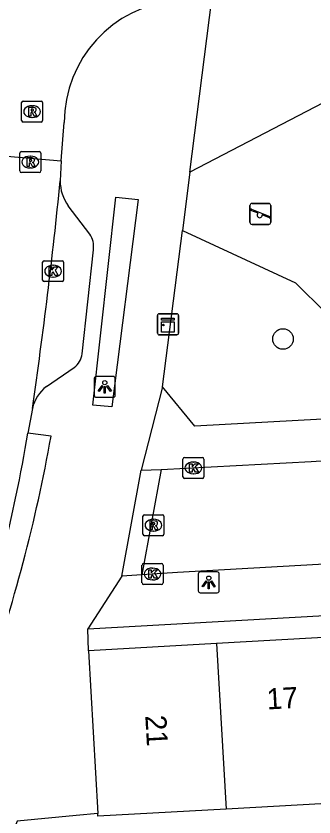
# Model space of a CAD drawing. Extents: x 163010 to 163853, y 382793 to 383982.
# Drawn here: x 163432.08 to 163446.26, y 383532.53 to 383570.74 of the extents above; entities that cross this region are included whole.
import ezdxf

# ---------------------------------------------------------------- set-up
doc = ezdxf.new("R2010")
doc.units = 0
for name, color, linetype in [('IMGEO_Boom', 7, 'Continuous'), ('IMGEO_Groenvoorziening', 7, 'Continuous'), ('IMGEO_Hek', 7, 'Continuous'), ('IMGEO_Kast', 7, 'Continuous'), ('IMGEO_Kolk', 7, 'Continuous'), ('IMGEO_Lichtpunt', 7, 'Continuous'), ('IMGEO_Pand', 7, 'Continuous'), ('IMGEO_Pand_nummerreeks', 7, 'Continuous'), ('IMGEO_Rijbaan_lokaal_gesloten', 7, 'Continuous'), ('IMGEO_Rijbaan_lokaal_open', 7, 'Continuous'), ('IMGEO_Rioolput', 7, 'Continuous'), ('IMGEO_Speelvoorziening', 7, 'Continuous'), ('IMGEO_Voetpad_open', 7, 'Continuous')]:
    doc.layers.add(name, color=color, linetype=linetype)

msp = doc.modelspace()

# ---------------------------------------------------------------- linework, layer by layer
at = {"layer": 'IMGEO_Boom'}
msp.add_circle((163444.789, 383555.331), 0.489, dxfattribs=at)
at = {"layer": 'IMGEO_Groenvoorziening'}
msp.add_lwpolyline([(163440, 383560.499), (163445.378, 383558.006), (163448.277, 383555.144)], dxfattribs=at)
at = {"layer": 'IMGEO_Hek'}
msp.add_lwpolyline([(163451.072, 383568.864), (163440.352, 383563.287)], dxfattribs=at)
at = {"layer": 'IMGEO_Kast'}
for p, q in [((163438.816, 383555.607), (163438.816, 383556.448)), ((163438.816, 383556.448), (163438.816, 383555.607)), ((163438.891, 383556.532), (163439.732, 383556.532)), ((163439.732, 383556.532), (163438.891, 383556.532)), ((163439.816, 383556.457), (163439.816, 383555.616)), ((163439.816, 383555.616), (163439.816, 383556.457)), ((163439.741, 383555.532), (163438.9, 383555.532)), ((163438.9, 383555.532), (163439.741, 383555.532))]:
    msp.add_line(p, q, dxfattribs=at)
for points in [[(163439.011, 383556.322), (163439.611, 383556.322), (163439.611, 383556.237), (163439.011, 383556.237), (163439.011, 383556.322)], [(163439.011, 383556.147), (163439.611, 383556.147), (163439.611, 383555.658), (163439.011, 383555.658), (163439.011, 383556.147)]]:
    msp.add_lwpolyline(points, dxfattribs=at)
msp.add_circle((163439.095, 383555.996), 0.0377, dxfattribs=at)
for centre, start, end in [((163438.894, 383556.454), 92.4484, 184.2845), ((163438.894, 383556.454), 92.4484, 184.2845), ((163439.738, 383556.454), 2.4484, 94.2845), ((163439.738, 383556.454), 2.4484, 94.2845), ((163438.894, 383555.61), 182.4484, 274.2845), ((163438.894, 383555.61), 182.4484, 274.2845), ((163439.738, 383555.61), 272.4484, 4.2845), ((163439.738, 383555.61), 272.4484, 4.2845)]:
    msp.add_arc(centre, 0.0779, start, end, dxfattribs=at)
at = {"layer": 'IMGEO_Kolk'}
for p, q in [((163433.342, 383558.14), (163433.342, 383558.992)), ((163433.417, 383559.066), (163434.269, 383559.066)), ((163434.343, 383558.992), (163434.343, 383558.14)), ((163433.83, 383558.846), (163433.855, 383558.846)), ((163433.853, 383558.286), (163433.828, 383558.286)), ((163434.269, 383558.066), (163433.417, 383558.066)), ((163440.023, 383548.755), (163440.023, 383549.607)), ((163440.098, 383549.681), (163440.95, 383549.681)), ((163440.511, 383549.461), (163440.536, 383549.461)), ((163441.024, 383549.607), (163441.024, 383548.755)), ((163440.95, 383548.681), (163440.098, 383548.681)), ((163440.534, 383548.901), (163440.509, 383548.901)), ((163438.076, 383543.696), (163438.076, 383544.548)), ((163438.151, 383544.622), (163439.003, 383544.622)), ((163439.077, 383544.548), (163439.077, 383543.696)), ((163438.564, 383544.402), (163438.589, 383544.402)), ((163438.587, 383543.842), (163438.562, 383543.842)), ((163439.003, 383543.622), (163438.151, 383543.622))]:
    msp.add_line(p, q, dxfattribs=at)
for points in [[(163433.342, 383558.14), (163433.342, 383558.992)], [(163433.417, 383559.066), (163434.269, 383559.066)], [(163434.343, 383558.992), (163434.343, 383558.14)], [(163433.663, 383558.766), (163433.786, 383558.766), (163433.786, 383558.615), (163433.916, 383558.766), (163434.08, 383558.766), (163433.934, 383558.615), (163434.087, 383558.366), (163433.935, 383558.366), (163433.85, 383558.53), (163433.786, 383558.463), (163433.786, 383558.366), (163433.663, 383558.366), (163433.663, 383558.766)], [(163434.269, 383558.066), (163433.417, 383558.066)], [(163440.023, 383548.755), (163440.023, 383549.607)], [(163440.098, 383549.681), (163440.95, 383549.681)], [(163441.024, 383549.607), (163441.024, 383548.755)], [(163440.344, 383549.381), (163440.467, 383549.381), (163440.467, 383549.23), (163440.597, 383549.381), (163440.761, 383549.381), (163440.615, 383549.23), (163440.768, 383548.981), (163440.616, 383548.981), (163440.531, 383549.145), (163440.467, 383549.078), (163440.467, 383548.981), (163440.344, 383548.981), (163440.344, 383549.381)], [(163440.95, 383548.681), (163440.098, 383548.681)], [(163438.076, 383543.696), (163438.076, 383544.548)], [(163438.151, 383544.622), (163439.003, 383544.622)], [(163439.077, 383544.548), (163439.077, 383543.696)], [(163438.397, 383544.322), (163438.52, 383544.322), (163438.52, 383544.171), (163438.65, 383544.322), (163438.814, 383544.322), (163438.668, 383544.171), (163438.821, 383543.922), (163438.669, 383543.922), (163438.584, 383544.086), (163438.52, 383544.019), (163438.52, 383543.922), (163438.397, 383543.922), (163438.397, 383544.322)], [(163439.003, 383543.622), (163438.151, 383543.622)]]:
    msp.add_lwpolyline(points, dxfattribs=at)
for centre, start, end in [((163433.419, 383558.99), 91.552, 178.448), ((163433.419, 383558.99), 91.552, 178.448), ((163434.267, 383558.99), 1.552, 88.448), ((163434.267, 383558.99), 1.552, 88.448), ((163433.419, 383558.142), 181.552, 268.448), ((163433.419, 383558.142), 181.552, 268.448), ((163434.267, 383558.142), 271.552, 358.448), ((163434.267, 383558.142), 271.552, 358.448), ((163440.1, 383549.605), 91.552, 178.448), ((163440.1, 383549.605), 91.552, 178.448), ((163440.948, 383549.605), 1.552, 88.448), ((163440.948, 383549.605), 1.552, 88.448), ((163440.1, 383548.757), 181.552, 268.448), ((163440.1, 383548.757), 181.552, 268.448), ((163440.948, 383548.757), 271.552, 358.448), ((163440.948, 383548.757), 271.552, 358.448), ((163438.153, 383544.546), 91.552, 178.448), ((163438.153, 383544.546), 91.552, 178.448), ((163439.001, 383544.546), 1.552, 88.448), ((163439.001, 383544.546), 1.552, 88.448), ((163438.153, 383543.698), 181.552, 268.448), ((163438.153, 383543.698), 181.552, 268.448), ((163439.001, 383543.698), 271.552, 358.448), ((163439.001, 383543.698), 271.552, 358.448)]:
    msp.add_arc(centre, 0.0765, start, end, dxfattribs=at)
for centre, major_axis, ratio, start_param, end_param in [((163433.829, 383558.566), (-0.387, 0.002), 0.722429, 4.712389, 7.853982), ((163433.854, 383558.566), (-0.39, 0.002), 0.717154, 1.570796, 4.712389), ((163440.51, 383549.181), (-0.387, 0.002), 0.722429, 4.712389, 7.853982), ((163440.535, 383549.181), (-0.39, 0.002), 0.717154, 1.570796, 4.712389), ((163438.563, 383544.122), (-0.387, 0.002), 0.722429, 4.712389, 7.853982), ((163438.588, 383544.122), (-0.39, 0.002), 0.717154, 1.570796, 4.712389)]:
    msp.add_ellipse(centre, major_axis=major_axis, ratio=ratio, start_param=start_param, end_param=end_param, dxfattribs=at)
at = {"layer": 'IMGEO_Lichtpunt'}
for p, q in [((163435.805, 383553.451), (163435.805, 383552.644)), ((163435.805, 383553.451), (163435.805, 383552.644)), ((163436.707, 383553.546), (163435.899, 383553.546)), ((163436.707, 383553.546), (163435.899, 383553.546)), ((163436.801, 383552.644), (163436.801, 383553.451)), ((163436.801, 383552.644), (163436.801, 383553.451)), ((163435.899, 383552.55), (163436.707, 383552.55)), ((163435.899, 383552.55), (163436.707, 383552.55)), ((163440.757, 383544.128), (163440.757, 383543.321)), ((163440.757, 383544.128), (163440.757, 383543.321)), ((163441.659, 383544.223), (163440.851, 383544.223)), ((163441.659, 383544.223), (163440.851, 383544.223)), ((163441.753, 383543.321), (163441.753, 383544.128)), ((163441.753, 383543.321), (163441.753, 383544.128)), ((163440.851, 383543.227), (163441.659, 383543.227)), ((163440.851, 383543.227), (163441.659, 383543.227))]:
    msp.add_line(p, q, dxfattribs=at)
for points in [[(163436.179, 383553.115), (163436.218, 383553.087), (163436.03, 383552.825), (163435.992, 383552.852), (163436.179, 383553.115)], [(163436.281, 383553.067), (163436.328, 383553.067), (163436.328, 383552.745), (163436.281, 383552.745), (163436.281, 383553.067)], [(163436.391, 383553.087), (163436.429, 383553.114), (163436.616, 383552.852), (163436.577, 383552.824), (163436.391, 383553.087)], [(163441.131, 383543.792), (163441.17, 383543.764), (163440.982, 383543.502), (163440.944, 383543.529), (163441.131, 383543.792)], [(163441.233, 383543.744), (163441.28, 383543.744), (163441.28, 383543.422), (163441.233, 383543.422), (163441.233, 383543.744)], [(163441.343, 383543.764), (163441.381, 383543.791), (163441.568, 383543.529), (163441.529, 383543.501), (163441.343, 383543.764)]]:
    msp.add_lwpolyline(points, dxfattribs=at)
for centre in [(163436.304, 383553.249), (163441.256, 383543.926)]:
    msp.add_circle(centre, 0.0994, dxfattribs=at)
for centre, start, end in [((163435.899, 383553.451), 90, 180), ((163435.899, 383553.451), 90, 180), ((163436.707, 383553.451), 0, 90), ((163436.707, 383553.451), 0, 90), ((163435.899, 383552.644), 180, 270), ((163435.899, 383552.644), 180, 270), ((163436.707, 383552.644), 270, 0), ((163436.707, 383552.644), 270, 360), ((163440.851, 383544.128), 90, 180), ((163440.851, 383544.128), 90, 180), ((163441.659, 383544.128), 0, 90), ((163441.659, 383544.128), 0, 90), ((163440.851, 383543.321), 180, 270), ((163440.851, 383543.321), 180, 270), ((163441.659, 383543.321), 270, 0), ((163441.659, 383543.321), 270, 360)]:
    msp.add_arc(centre, 0.0946, start, end, dxfattribs=at)
at = {"layer": 'IMGEO_Pand'}
for points in [[(163447.554, 383541.141), (163441.631, 383540.807)], [(163441.631, 383540.807), (163435.533, 383540.463)], [(163441.631, 383540.807), (163442.077, 383532.908)], [(163435.533, 383540.463), (163435.97, 383532.7)], [(163448, 383533.242), (163442.077, 383532.908)], [(163442.077, 383532.908), (163435.978, 383532.564), (163435.97, 383532.7)]]:
    msp.add_lwpolyline(points, dxfattribs=at)
at = {"layer": 'IMGEO_Rijbaan_lokaal_gesloten'}
for points in [[(163434.229, 383563.823), (163434.377, 383565.655)], [(163429.219, 383564.263), (163434.229, 383563.823)], [(163434.229, 383563.823), (163434.181, 383562.874)], [(163432.854, 383552.021), (163432.637, 383550.845)], [(163433.747, 383550.691), (163432.637, 383550.845)]]:
    msp.add_lwpolyline(points, dxfattribs=at)
for centre, radius, start, end in [((163440.236, 383565.649), 5.859, 95.4042, 179.9438), ((163201.568, 383585.808), 233.741, 351.68883, 354.36923), ((163371.589, 383560.628), 61.827, 339.71664, 350.89551), ((163359.152, 383564.014), 75.776, 340.54735, 349.87321)]:
    msp.add_arc(centre, radius, start, end, dxfattribs=at)
at = {"layer": 'IMGEO_Rijbaan_lokaal_open'}
for points in [[(163438.996, 383549.105), (163446.126, 383549.486), (163457.78, 383550.265), (163474.503, 383551.227), (163492.842, 383552.254), (163495.537, 383552.438)], [(163437.117, 383544.023), (163438.03, 383549.068)], [(163438.03, 383549.068), (163438.996, 383549.105)], [(163438.996, 383549.105), (163438.069, 383544.085)], [(163496.534, 383547.428), (163439.769, 383544.193), (163438.069, 383544.085)], [(163438.069, 383544.085), (163437.117, 383544.023)]]:
    msp.add_lwpolyline(points, dxfattribs=at)
at = {"layer": 'IMGEO_Rioolput'}
for p, q in [((163432.341, 383565.752), (163432.341, 383566.604)), ((163432.416, 383566.678), (163433.268, 383566.678)), ((163433.342, 383566.604), (163433.342, 383565.752)), ((163432.829, 383566.458), (163432.854, 383566.458)), ((163432.852, 383565.898), (163432.827, 383565.898)), ((163433.268, 383565.678), (163432.416, 383565.678)), ((163432.256, 383563.346), (163432.256, 383564.198)), ((163432.331, 383564.272), (163433.183, 383564.272)), ((163432.744, 383564.052), (163432.769, 383564.052)), ((163433.257, 383564.198), (163433.257, 383563.346)), ((163433.183, 383563.272), (163432.331, 383563.272)), ((163432.767, 383563.492), (163432.742, 383563.492)), ((163438.12, 383546.024), (163438.12, 383546.876)), ((163438.195, 383546.95), (163439.047, 383546.95)), ((163438.608, 383546.73), (163438.633, 383546.73)), ((163439.121, 383546.876), (163439.121, 383546.024)), ((163439.047, 383545.95), (163438.195, 383545.95)), ((163438.631, 383546.17), (163438.606, 383546.17))]:
    msp.add_line(p, q, dxfattribs=at)
for points in [[(163432.341, 383565.752), (163432.341, 383566.604)], [(163432.416, 383566.678), (163433.268, 383566.678)], [(163433.342, 383566.604), (163433.342, 383565.752)], [(163432.93, 383566.376), (163432.678, 383566.378), (163432.678, 383565.978)], [(163432.856, 383566.297), (163432.802, 383566.297), (163432.802, 383566.216)], [(163432.802, 383566.216), (163432.854, 383566.216)], [(163432.678, 383565.978), (163432.802, 383565.978), (163432.802, 383566.14), (163432.813, 383566.14)], [(163432.86, 383566.111), (163432.931, 383565.978), (163433.071, 383565.978), (163433.006, 383566.104)], [(163433.268, 383565.678), (163432.416, 383565.678)], [(163432.256, 383563.346), (163432.256, 383564.198)], [(163432.331, 383564.272), (163433.183, 383564.272)], [(163432.845, 383563.97), (163432.593, 383563.972), (163432.593, 383563.572)], [(163433.257, 383564.198), (163433.257, 383563.346)], [(163432.593, 383563.572), (163432.717, 383563.572), (163432.717, 383563.734), (163432.728, 383563.734)], [(163432.771, 383563.891), (163432.717, 383563.891), (163432.717, 383563.81)], [(163432.717, 383563.81), (163432.769, 383563.81)], [(163432.775, 383563.705), (163432.846, 383563.572), (163432.986, 383563.572), (163432.921, 383563.698)], [(163433.183, 383563.272), (163432.331, 383563.272)], [(163438.12, 383546.024), (163438.12, 383546.876)], [(163438.195, 383546.95), (163439.047, 383546.95)], [(163439.121, 383546.876), (163439.121, 383546.024)], [(163438.709, 383546.648), (163438.457, 383546.65), (163438.457, 383546.25)], [(163438.457, 383546.25), (163438.581, 383546.25), (163438.581, 383546.412), (163438.592, 383546.412)], [(163438.635, 383546.569), (163438.581, 383546.569), (163438.581, 383546.488)], [(163438.581, 383546.488), (163438.633, 383546.488)], [(163438.639, 383546.383), (163438.71, 383546.25), (163438.85, 383546.25), (163438.785, 383546.376)], [(163439.047, 383545.95), (163438.195, 383545.95)]]:
    msp.add_lwpolyline(points, dxfattribs=at)
for centre, radius, start, end in [((163432.418, 383566.602), 0.0765, 91.552, 178.448), ((163432.418, 383566.602), 0.0765, 91.552, 178.448), ((163433.266, 383566.602), 0.0765, 1.552, 88.448), ((163433.266, 383566.602), 0.0765, 1.552, 88.448), ((163432.838, 383566.405), 0.19, 274.7715, 282.9687), ((163432.862, 383566.201), 0.0964, 77.0061, 93.1865), ((163432.876, 383566.258), 0.0378, 276.6634, 79.6772), ((163432.929, 383566.266), 0.109, 350.3612, 89.416), ((163432.927, 383566.266), 0.112, 277.5842, 350.9817), ((163432.812, 383566.087), 0.0533, 26.0293, 88.6989), ((163432.911, 383566.051), 0.108, 29.5134, 73.7905), ((163432.418, 383565.754), 0.0765, 181.552, 268.448), ((163432.418, 383565.754), 0.0765, 181.552, 268.448), ((163433.266, 383565.754), 0.0765, 271.552, 358.448), ((163433.266, 383565.754), 0.0765, 271.552, 358.448), ((163432.333, 383564.196), 0.0765, 91.552, 178.448), ((163432.333, 383564.196), 0.0765, 91.552, 178.448), ((163432.844, 383563.86), 0.109, 350.3612, 89.416), ((163433.181, 383564.196), 0.0765, 1.552, 88.448), ((163433.181, 383564.196), 0.0765, 1.552, 88.448), ((163432.727, 383563.681), 0.0533, 26.0293, 88.6989), ((163432.753, 383563.999), 0.19, 274.7715, 282.9687), ((163432.777, 383563.795), 0.0964, 77.0061, 93.1865), ((163432.791, 383563.852), 0.0378, 276.6634, 79.6772), ((163432.842, 383563.86), 0.112, 277.5842, 350.9817), ((163432.826, 383563.645), 0.108, 29.5134, 73.7905), ((163432.333, 383563.348), 0.0765, 181.552, 268.448), ((163432.333, 383563.348), 0.0765, 181.552, 268.448), ((163433.181, 383563.348), 0.0765, 271.552, 358.448), ((163433.181, 383563.348), 0.0765, 271.552, 358.448), ((163438.197, 383546.874), 0.0765, 91.552, 178.448), ((163438.197, 383546.874), 0.0765, 91.552, 178.448), ((163439.045, 383546.874), 0.0765, 1.552, 88.448), ((163439.045, 383546.874), 0.0765, 1.552, 88.448), ((163438.591, 383546.359), 0.0533, 26.0293, 88.6989), ((163438.617, 383546.677), 0.19, 274.7715, 282.9687), ((163438.641, 383546.473), 0.0964, 77.0061, 93.1865), ((163438.655, 383546.53), 0.0378, 276.6634, 79.6772), ((163438.708, 383546.538), 0.109, 350.3612, 89.416), ((163438.706, 383546.538), 0.112, 277.5842, 350.9817), ((163438.69, 383546.323), 0.108, 29.5134, 73.7905), ((163438.197, 383546.026), 0.0765, 181.552, 268.448), ((163438.197, 383546.026), 0.0765, 181.552, 268.448), ((163439.045, 383546.026), 0.0765, 271.552, 358.448), ((163439.045, 383546.026), 0.0765, 271.552, 358.448)]:
    msp.add_arc(centre, radius, start, end, dxfattribs=at)
for centre, major_axis, ratio, start_param, end_param in [((163432.828, 383566.178), (-0.387, 0.002), 0.722429, 4.712389, 7.853982), ((163432.853, 383566.178), (-0.39, 0.002), 0.717154, 1.570796, 4.712389), ((163432.743, 383563.772), (-0.387, 0.002), 0.722429, 4.712389, 7.853982), ((163432.768, 383563.772), (-0.39, 0.002), 0.717154, 1.570796, 4.712389), ((163438.607, 383546.45), (-0.387, 0.002), 0.722429, 4.712389, 7.853982), ((163438.632, 383546.45), (-0.39, 0.002), 0.717154, 1.570796, 4.712389)]:
    msp.add_ellipse(centre, major_axis=major_axis, ratio=ratio, start_param=start_param, end_param=end_param, dxfattribs=at)
at = {"layer": 'IMGEO_Speelvoorziening'}
for p, q in [((163443.219, 383560.899), (163443.219, 383561.699)), ((163443.219, 383561.699), (163443.219, 383560.899)), ((163443.319, 383561.799), (163444.109, 383561.799)), ((163444.109, 383561.799), (163443.319, 383561.799)), ((163444.209, 383561.699), (163444.209, 383560.899)), ((163444.209, 383560.899), (163444.209, 383561.699)), ((163443.602, 383561.327), (163443.263, 383561.464)), ((163443.288, 383561.524), (163444.164, 383561.171)), ((163444.14, 383561.111), (163443.8, 383561.248)), ((163444.109, 383560.799), (163443.319, 383560.799)), ((163443.319, 383560.799), (163444.109, 383560.799))]:
    msp.add_line(p, q, dxfattribs=at)
for centre, radius, start, end in [((163443.319, 383561.699), 0.1, 90, 180), ((163443.319, 383561.699), 0.1, 90, 180), ((163444.109, 383561.699), 0.1, 0, 90), ((163444.109, 383561.699), 0.1, 360, 90), ((163443.276, 383561.494), 0.0327, 68.078, 248.078), ((163443.681, 383561.237), 0.12, 130.9928, 5.1632), ((163443.319, 383560.899), 0.1, 180, 270), ((163443.319, 383560.899), 0.1, 180, 270), ((163444.109, 383560.899), 0.1, 270, 0), ((163444.109, 383560.899), 0.1, 270, 0), ((163444.152, 383561.141), 0.0327, 248.078, 68.078)]:
    msp.add_arc(centre, radius, start, end, dxfattribs=at)
at = {"layer": 'IMGEO_Voetpad_open'}
for points in [[(163440.352, 383563.287), (163441.396, 383571.559)], [(163451.072, 383568.864), (163440.352, 383563.287)], [(163440.352, 383563.287), (163440, 383560.499)], [(163436.836, 383562.092), (163437.896, 383561.988), (163436.643, 383552.089), (163435.728, 383552.169), (163436.836, 383562.092)], [(163435.592, 383560.333), (163434.561, 383561.683)], [(163439.058, 383553.042), (163440, 383560.499)], [(163435.234, 383554.619), (163435.763, 383559.584)], [(163433.528, 383553.067), (163434.842, 383553.976)], [(163439.058, 383553.042), (163438.03, 383549.068)], [(163446.672, 383551.512), (163440.585, 383551.167), (163439.058, 383553.042)], [(163435.502, 383541.51), (163495.019, 383544.868)], [(163437.117, 383544.023), (163435.502, 383541.51)], [(163435.533, 383540.463), (163435.502, 383541.51)], [(163435.97, 383532.7), (163434.943, 383532.603), (163432.139, 383532.338), (163429.633, 383526.219)]]:
    msp.add_lwpolyline(points, dxfattribs=at)
for centre, radius, start, end in [((163436.189, 383562.858), 2.008, 179.5575, 215.8341), ((163434.702, 383559.736), 1.072, 351.8572, 33.8637), ((163434.25, 383554.778), 0.997, 306.4436, 350.8199), ((163434.755, 383551.536), 1.962, 128.7192, 165.6887)]:
    msp.add_arc(centre, radius, start, end, dxfattribs=at)

# ---------------------------------------------------------------- texts
at = {"layer": 'IMGEO_Pand_nummerreeks'}
for s, rotation, p in [('17', 3.2291, (163444.043, 383537.658)), ('21', 273.2244, (163438.231, 383537.368))]:
    msp.add_text(s, height=1, rotation=rotation, dxfattribs=at).set_placement(p)

doc.saveas('drawing.dxf')
